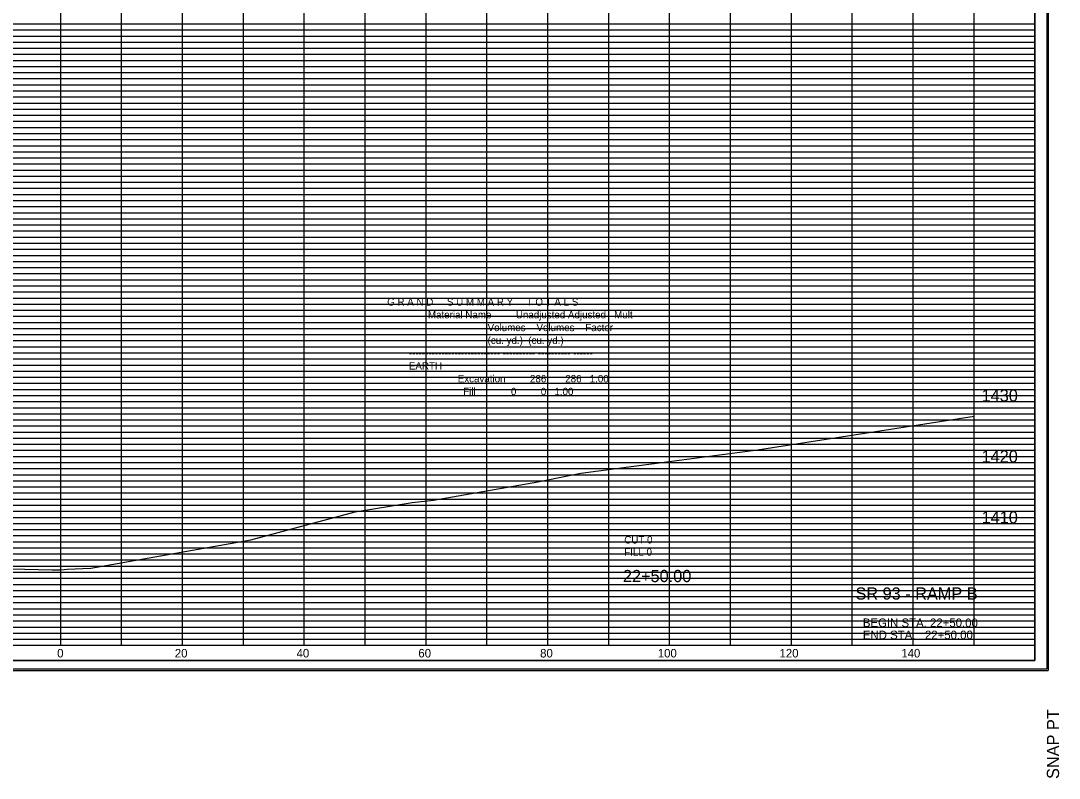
# Model space of a CAD drawing. Extents: x 980 to 1324, y 978 to 1497.
# Drawn here: x 1153.4 to 1324, y 1248.2 to 1372.5 of the extents above; entities that cross this region are included whole.
import ezdxf

# ---------------------------------------------------------------- set-up
doc = ezdxf.new("R2010")
doc.units = 0
for name, color, linetype in [('DESIGN - SHEET - Corner Text', 7, 'Continuous'), ('DESIGN - SHEET - Light Grid', 7, 'Continuous'), ('DESIGN - SHEET - Linework', 7, 'Continuous'), ('DESIGN - SHEET - Plot Shape', 7, 'Continuous'), ('DESIGN - TYPICAL - Text', 7, 'Continuous'), ('SURVEY - GROUND - Top of Ground', 7, 'Continuous')]:
    doc.layers.add(name, color=color, linetype=linetype)

# ---------------------------------------------------------------- blocks, each defined once
blk = doc.blocks.new('XSTSHT')
at = {"layer": 'DESIGN - SHEET - Light Grid'}
for p, q in [((8, 10.2), (16, 10.2)), ((8, 10.1), (16, 10.1)), ((16, 10.2), (24, 10.2)), ((16, 10.1), (24, 10.1)), ((24, 10.2), (32, 10.2)), ((24, 10.1), (32, 10.1)), ((8, 9.9), (16, 9.9)), ((16, 9.9), (24, 9.9)), ((24, 9.9), (32, 9.9)), ((8, 9.8), (16, 9.8)), ((16, 9.8), (24, 9.8)), ((24, 9.8), (32, 9.8)), ((8, 9.7), (16, 9.7)), ((8, 9.6), (16, 9.6)), ((16, 9.7), (24, 9.7)), ((16, 9.6), (24, 9.6)), ((24, 9.7), (32, 9.7)), ((24, 9.6), (32, 9.6)), ((8, 9.5), (16, 9.5)), ((8, 9.4), (16, 9.4)), ((16, 9.5), (24, 9.5)), ((16, 9.4), (24, 9.4)), ((24, 9.5), (32, 9.5)), ((24, 9.4), (32, 9.4)), ((8, 9.3), (16, 9.3)), ((16, 9.3), (24, 9.3)), ((24, 9.3), (32, 9.3)), ((8, 9.2), (16, 9.2)), ((8, 9.1), (16, 9.1)), ((16, 9.2), (24, 9.2)), ((16, 9.1), (24, 9.1)), ((24, 9.2), (32, 9.2)), ((24, 9.1), (32, 9.1)), ((8, 8.9), (16, 8.9)), ((16, 8.9), (24, 8.9)), ((24, 8.9), (32, 8.9)), ((8, 8.8), (16, 8.8)), ((8, 8.7), (16, 8.7)), ((16, 8.8), (24, 8.8)), ((16, 8.7), (24, 8.7)), ((24, 8.8), (32, 8.8)), ((24, 8.7), (32, 8.7)), ((8, 8.6), (16, 8.6)), ((16, 8.6), (24, 8.6)), ((24, 8.6), (32, 8.6)), ((8, 8.5), (16, 8.5)), ((8, 8.4), (16, 8.4)), ((16, 8.5), (24, 8.5)), ((16, 8.4), (24, 8.4)), ((24, 8.5), (32, 8.5)), ((24, 8.4), (32, 8.4)), ((8, 8.3), (16, 8.3)), ((8, 8.2), (16, 8.2)), ((16, 8.3), (24, 8.3)), ((16, 8.2), (24, 8.2)), ((24, 8.3), (32, 8.3)), ((24, 8.2), (32, 8.2)), ((8, 8.1), (16, 8.1)), ((16, 8.1), (24, 8.1)), ((24, 8.1), (32, 8.1)), ((8, 7.9), (16, 7.9)), ((16, 7.9), (24, 7.9)), ((24, 7.9), (32, 7.9)), ((8, 7.8), (16, 7.8)), ((8, 7.7), (16, 7.7)), ((16, 7.8), (24, 7.8)), ((16, 7.7), (24, 7.7)), ((24, 7.8), (32, 7.8)), ((24, 7.7), (32, 7.7)), ((8, 7.6), (16, 7.6)), ((16, 7.6), (24, 7.6)), ((24, 7.6), (32, 7.6)), ((8, 7.5), (16, 7.5)), ((8, 7.4), (16, 7.4)), ((16, 7.5), (24, 7.5)), ((16, 7.4), (24, 7.4)), ((24, 7.5), (32, 7.5)), ((24, 7.4), (32, 7.4)), ((8, 7.3), (16, 7.3)), ((8, 7.2), (16, 7.2)), ((16, 7.3), (24, 7.3)), ((16, 7.2), (24, 7.2)), ((24, 7.3), (32, 7.3)), ((24, 7.2), (32, 7.2)), ((8, 7.1), (16, 7.1)), ((16, 7.1), (24, 7.1)), ((24, 7.1), (32, 7.1)), ((8, 6.9), (16, 6.9)), ((16, 6.9), (24, 6.9)), ((24, 6.9), (32, 6.9)), ((8, 6.8), (16, 6.8)), ((8, 6.7), (16, 6.7)), ((16, 6.8), (24, 6.8)), ((16, 6.7), (24, 6.7)), ((24, 6.8), (32, 6.8)), ((24, 6.7), (32, 6.7)), ((8, 6.6), (16, 6.6)), ((8, 6.5), (16, 6.5)), ((16, 6.6), (24, 6.6)), ((16, 6.5), (24, 6.5)), ((24, 6.6), (32, 6.6)), ((24, 6.5), (32, 6.5)), ((8, 6.4), (16, 6.4)), ((16, 6.4), (24, 6.4)), ((24, 6.4), (32, 6.4)), ((8, 6.3), (16, 6.3)), ((8, 6.2), (16, 6.2)), ((16, 6.3), (24, 6.3)), ((16, 6.2), (24, 6.2)), ((24, 6.3), (32, 6.3)), ((24, 6.2), (32, 6.2)), ((8, 6.1), (16, 6.1)), ((16, 6.1), (24, 6.1)), ((24, 6.1), (32, 6.1)), ((8, 5.9), (16, 5.9)), ((8, 5.8), (16, 5.8)), ((16, 5.9), (24, 5.9)), ((16, 5.8), (24, 5.8)), ((24, 5.9), (32, 5.9)), ((24, 5.8), (32, 5.8)), ((8, 5.7), (16, 5.7)), ((16, 5.7), (24, 5.7)), ((24, 5.7), (32, 5.7)), ((8, 5.6), (16, 5.6)), ((8, 5.5), (16, 5.5)), ((16, 5.6), (24, 5.6)), ((16, 5.5), (24, 5.5)), ((24, 5.6), (32, 5.6)), ((24, 5.5), (32, 5.5)), ((8, 5.4), (16, 5.4)), ((8, 5.3), (16, 5.3)), ((16, 5.4), (24, 5.4)), ((16, 5.3), (24, 5.3)), ((24, 5.4), (32, 5.4)), ((24, 5.3), (32, 5.3)), ((8, 5.2), (16, 5.2)), ((16, 5.2), (24, 5.2)), ((24, 5.2), (32, 5.2)), ((8, 5.1), (16, 5.1)), ((16, 5.1), (24, 5.1)), ((24, 5.1), (32, 5.1)), ((8, 4.9), (16, 4.9)), ((8, 4.8), (16, 4.8)), ((16, 4.9), (24, 4.9)), ((16, 4.8), (24, 4.8)), ((24, 4.9), (32, 4.9)), ((24, 4.8), (32, 4.8)), ((8, 4.7), (16, 4.7)), ((16, 4.7), (24, 4.7)), ((24, 4.7), (32, 4.7)), ((8, 4.6), (16, 4.6)), ((8, 4.5), (16, 4.5)), ((16, 4.6), (24, 4.6)), ((16, 4.5), (24, 4.5)), ((24, 4.6), (32, 4.6)), ((24, 4.5), (32, 4.5)), ((8, 4.4), (16, 4.4)), ((8, 4.3), (16, 4.3)), ((16, 4.4), (24, 4.4)), ((16, 4.3), (24, 4.3)), ((24, 4.4), (32, 4.4)), ((24, 4.3), (32, 4.3)), ((8, 4.2), (16, 4.2)), ((8, 4.1), (16, 4.1)), ((16, 4.2), (24, 4.2)), ((16, 4.1), (24, 4.1)), ((24, 4.2), (32, 4.2)), ((24, 4.1), (32, 4.1)), ((8, 3.9), (16, 3.9)), ((8, 3.8), (16, 3.8)), ((16, 3.9), (24, 3.9)), ((16, 3.8), (24, 3.8)), ((24, 3.9), (32, 3.9)), ((24, 3.8), (32, 3.8)), ((8, 3.7), (16, 3.7)), ((8, 3.6), (16, 3.6)), ((16, 3.7), (24, 3.7)), ((16, 3.6), (24, 3.6)), ((24, 3.7), (32, 3.7)), ((24, 3.6), (32, 3.6)), ((8, 3.5), (16, 3.5)), ((16, 3.5), (24, 3.5)), ((24, 3.5), (32, 3.5)), ((8, 3.4), (16, 3.4)), ((8, 3.3), (16, 3.3)), ((16, 3.4), (24, 3.4)), ((16, 3.3), (24, 3.3)), ((24, 3.4), (32, 3.4)), ((24, 3.3), (32, 3.3)), ((8, 3.2), (16, 3.2)), ((8, 3.1), (16, 3.1)), ((16, 3.2), (24, 3.2)), ((16, 3.1), (24, 3.1)), ((24, 3.2), (32, 3.2)), ((24, 3.1), (32, 3.1)), ((8, 2.9), (16, 2.9)), ((16, 2.9), (24, 2.9)), ((24, 2.9), (32, 2.9)), ((8, 2.8), (16, 2.8)), ((16, 2.8), (24, 2.8)), ((24, 2.8), (32, 2.8)), ((8, 2.7), (16, 2.7)), ((8, 2.6), (16, 2.6)), ((16, 2.7), (24, 2.7)), ((16, 2.6), (24, 2.6)), ((24, 2.7), (32, 2.7)), ((24, 2.6), (32, 2.6)), ((8, 2.5), (16, 2.5)), ((8, 2.4), (16, 2.4)), ((16, 2.5), (24, 2.5)), ((16, 2.4), (24, 2.4)), ((24, 2.5), (32, 2.5)), ((24, 2.4), (32, 2.4)), ((8, 2.3), (16, 2.3)), ((16, 2.3), (24, 2.3)), ((24, 2.3), (32, 2.3)), ((8, 2.2), (16, 2.2)), ((8, 2.1), (16, 2.1)), ((16, 2.2), (24, 2.2)), ((16, 2.1), (24, 2.1)), ((24, 2.2), (32, 2.2)), ((24, 2.1), (32, 2.1)), ((8, 1.9), (16, 1.9)), ((16, 1.9), (24, 1.9)), ((24, 1.9), (32, 1.9)), ((8, 1.8), (16, 1.8)), ((16, 1.8), (24, 1.8)), ((24, 1.8), (32, 1.8)), ((8, 1.7), (16, 1.7)), ((8, 1.6), (16, 1.6)), ((16, 1.7), (24, 1.7)), ((16, 1.6), (24, 1.6)), ((24, 1.7), (32, 1.7)), ((24, 1.6), (32, 1.6)), ((8, 1.5), (16, 1.5)), ((8, 1.4), (16, 1.4)), ((16, 1.5), (24, 1.5)), ((16, 1.4), (24, 1.4)), ((24, 1.5), (32, 1.5)), ((24, 1.4), (32, 1.4)), ((8, 1.3), (16, 1.3)), ((8, 1.2), (16, 1.2)), ((16, 1.3), (24, 1.3)), ((16, 1.2), (24, 1.2)), ((24, 1.3), (32, 1.3)), ((24, 1.2), (32, 1.2)), ((8, 1.1), (16, 1.1)), ((16, 1.1), (24, 1.1)), ((24, 1.1), (32, 1.1)), ((8, 0.9), (16, 0.9)), ((16, 0.9), (24, 0.9)), ((24, 0.9), (32, 0.9)), ((8, 0.8), (16, 0.8)), ((8, 0.7), (16, 0.7)), ((16, 0.8), (24, 0.8)), ((16, 0.7), (24, 0.7)), ((24, 0.8), (32, 0.8)), ((24, 0.7), (32, 0.7)), ((8, 0.6), (16, 0.6)), ((16, 0.6), (24, 0.6)), ((24, 0.6), (32, 0.6)), ((8, 0.5), (16, 0.5)), ((8, 0.4), (16, 0.4)), ((16, 0.5), (24, 0.5)), ((16, 0.4), (24, 0.4)), ((24, 0.5), (32, 0.5)), ((24, 0.4), (32, 0.4)), ((8, 0.3), (16, 0.3)), ((8, 0.2), (16, 0.2)), ((16, 0.3), (24, 0.3)), ((16, 0.2), (24, 0.2)), ((24, 0.3), (32, 0.3)), ((24, 0.2), (32, 0.2)), ((8, 0.1), (16, 0.1)), ((16, 0.1), (24, 0.1)), ((24, 0.1), (32, 0.1))]:
    blk.add_line(p, q, dxfattribs=at)
at = {"layer": 'DESIGN - SHEET - Linework'}
for p, q in [((32.217, 21.414), (32.217, -0.414)), ((16, 0), (16, 21)), ((17, 0), (17, 21)), ((18, 0), (18, 21)), ((19, 0), (19, 21)), ((20, 0), (20, 21)), ((21, 0), (21, 21)), ((22, 0), (22, 21)), ((23, 0), (23, 21)), ((24, 0), (24, 21)), ((25, 0), (25, 21)), ((26, 0), (26, 21)), ((27, 0), (27, 21)), ((28, 0), (28, 20)), ((29, 0), (29, 20)), ((30, 0), (30, 20)), ((31, 0), (31, 20)), ((0, 10), (32, 10)), ((0, 9), (32, 9)), ((0, 8), (32, 8)), ((0, 7), (32, 7)), ((0, 6), (32, 6)), ((0, 5), (32, 5)), ((0, 4), (32, 4)), ((0, 3), (32, 3)), ((0, 2), (32, 2)), ((0, 1), (32, 1)), ((-1.823, -0.414), (32.217, -0.414))]:
    blk.add_line(p, q, dxfattribs=at)
blk.add_lwpolyline([(0, 21), (0, 0), (32, 0), (32, 21), (0, 21)], dxfattribs=at)
at = {"layer": 'DESIGN - SHEET - Plot Shape'}
for points in [[(-1.803, 21.394), (32.197, 21.394), (32.197, -0.394), (-1.803, -0.394)], [(-0.85, 21), (32, 21), (32, -0.25), (-0.85, -0.25)]]:
    blk.add_lwpolyline(points, close=True, dxfattribs=at)
at = {"layer": 'DESIGN - SHEET - Corner Text'}
blk.add_text('SNAP PT  ', height=0.2, rotation=90, dxfattribs=at).set_placement((32.397, -2.194))

msp = doc.modelspace()

# ---------------------------------------------------------------- linework, layer by layer
at = {"layer": 'DESIGN - SHEET - Plot Shape'}
msp.add_lwpolyline([(991.5, 1267.5), (1320, 1267.5), (1320, 1480), (991.5, 1480)], close=True, dxfattribs=at)
at = {"layer": 'SURVEY - GROUND - Top of Ground'}
msp.add_lwpolyline([(1151.84, 1282.57), (1158.57, 1282.4), (1160.09, 1282.37), (1161.04, 1282.49), (1164.93, 1282.68), (1191.25, 1287.31), (1208.38, 1291.93), (1217.73, 1293.45), (1221.24, 1293.84), (1238.34, 1296.85), (1243.52, 1297.84), (1245.44, 1298.23), (1274.45, 1302.09), (1310, 1307.62)], dxfattribs=at)

# ---------------------------------------------------------------- block references
at = {"layer": 'DESIGN - SHEET - Corner Text', "xscale": 10, "yscale": 10}
msp.add_blockref('XSTSHT', (1000, 1270), dxfattribs=at)

# ---------------------------------------------------------------- texts
at = {"layer": 'DESIGN - SHEET - Corner Text'}
for s, height, p in [('1430', 2, (1311.25, 1310)), ('1420', 2, (1311.25, 1300)), ('1410', 2, (1311.25, 1290)), ('22+50.00', 2, (1252.34, 1280.37)), ('SR 93 - RAMP B', 2, (1290.53, 1277.5)), ('BEGIN STA. 22+50.00', 1.4, (1291.75, 1273)), ('END STA.   22+50.00', 1.4, (1291.75, 1271)), ('0', 1.4, (1159.42, 1268)), ('0', 1.4, (1159.42, 1268)), ('20', 1.4, (1178.74, 1268)), ('40', 1.4, (1198.74, 1268)), ('60', 1.4, (1218.74, 1268)), ('80', 1.4, (1238.74, 1268)), ('100', 1.4, (1258.06, 1268)), ('120', 1.4, (1278.06, 1268)), ('140', 1.4, (1298.06, 1268))]:
    msp.add_text(s, height=height, dxfattribs=at).set_placement(p)
at = {"layer": 'DESIGN - TYPICAL - Text'}
for s, p in [('G R A N D     S U M M A R Y     T O T A L S', (1213.62, 1325.76)), ('               Material Name         Unadjusted Adjusted   Mult', (1213.62, 1323.66)), ('                                     Volumes    Volumes    Factor', (1213.62, 1321.56)), ('                                     (cu. yd.)  (cu. yd.)', (1213.62, 1319.46)), ('        ---------------------------- ---------- ---------- ------', (1213.62, 1317.36)), ('        EARTH', (1213.62, 1315.26)), ('                          Excavation         286       286   1.00', (1213.62, 1313.16)), ('                            Fill             0         0   1.00', (1213.62, 1311.06)), ('CUT 0', (1252.56, 1286.71)), ('FILL 0', (1252.56, 1284.71))]:
    msp.add_text(s, height=1.2, dxfattribs=at).set_placement(p)

doc.saveas('drawing.dxf')
